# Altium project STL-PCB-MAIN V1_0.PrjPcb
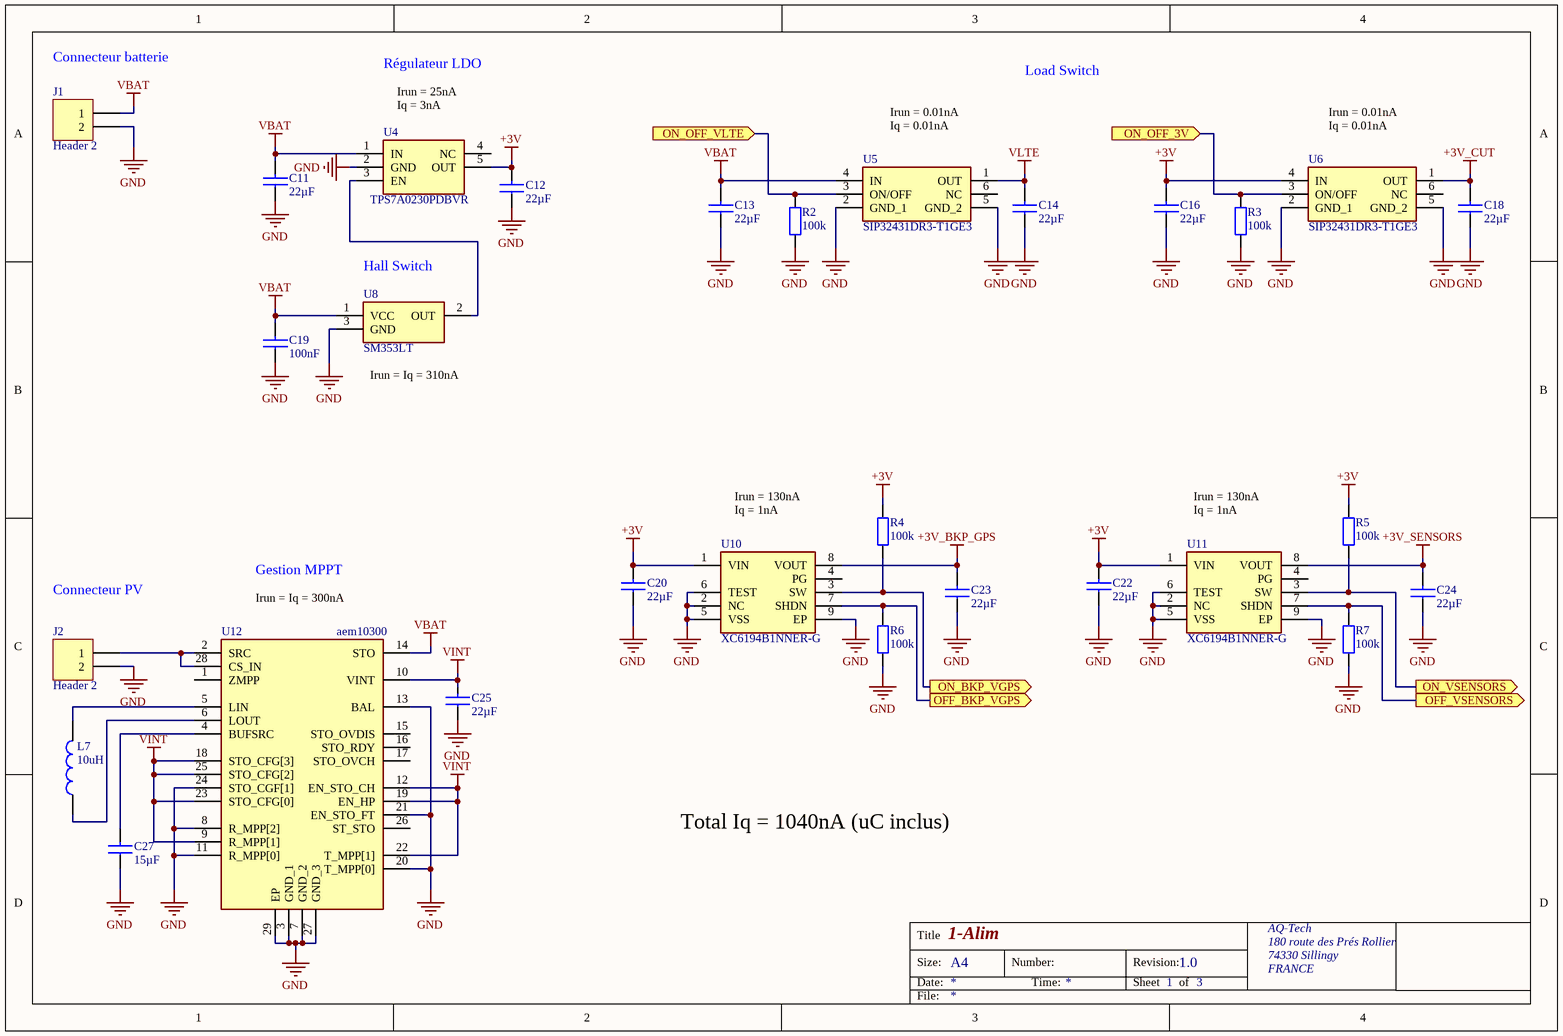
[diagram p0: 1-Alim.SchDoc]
Revision: 2.0
4 sheets, 79 parts. Net scope: flat (ports and power ports of the same name join across sheets).
Board file: STL-PCB-MAIN V1_0.PcbDoc
Sheets:
  1-Alim.SchDoc
  2-Micro.SchDoc
  3-Modules.SchDoc
  4-Capteurs.SchDoc

## Sheet 1-Alim.SchDoc: DEV-09-17 MERE
size A4; Date: 22/11/2017; Organization: Altium Limited; Address1: L3, 12a Rodborough Rd; Address2: Frenchs Forest; Address3: NSW; Address4: Australia 2086; Revision: 1.0; SheetNumber: 2; SheetTotal: 4; PageSetup: Record=PageOptions¦CenterHorizontal=True¦CenterVertical=True¦PrintScale=0.97¦XCorrection=1.00¦YCorrection=1.00¦PrintKind=0¦BorderSize=5000000¦LeftOffset=0¦BottomOffset=0¦Orientation=2¦PaperLength=1000¦PaperWidth=1000¦Scale=100¦PaperSource=7¦PrintQuality=-3¦MediaType=1¦DitherType=10¦PaperKind=A4¦PrintScaleMode=1

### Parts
C11  22µF  [CAP_0402_0H80]
C12  22µF  [CAP_0402_0H80]
C13  22µF  [CAP_0402_0H80]
C14  22µF  [CAP_0402_0H80]
C16  22µF  [CAP_0402_0H80]
C18  22µF  [CAP_0402_0H80]
C19  100nF  [CAP_0402_0H80]
C20  22µF  [CAP_0402_0H80]
C22  22µF  [CAP_0402_0H80]
C23  22µF  [CAP_0402_0H80]
C24  22µF  [CAP_0402_0H80]
C25  22µF  [CAP_0402_0H80]
C27  15µF  [CAP_0402_0H80]
J1  Header 2  [2PLAGES-2X1.3mm]
J2  Header 2  [2PLAGES-2X1.3mm]
L7  value 10uH  [VLS2520]  (hidden comment: DFE252010F-100M)
R2  100k  [RES_0402_0H65]
R3  100k  [RES_0402_0H65]
R4  100k  [RES_0402_0H65]
R5  100k  [RES_0402_0H65]
R6  100k  [RES_0402_0H65]
R7  100k  [RES_0402_0H65]
U4  TPS7A0230PDBVR  [TPS7A0230PDBVR-SOT23-5]
U5  SIP32431DR3-T1GE3  [SIP32431DR3-T1GE3]
U6  SIP32431DR3-T1GE3  [SIP32431DR3-T1GE3]
U8  SM353LT  [SOT23]
U10  XC6194B1NNER-G  [XC6194B1NNER-G]
U11  XC6194B1NNER-G  [XC6194B1NNER-G]
U12  aem10300  [AEM10300-QFN28-4X4mm]

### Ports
OFF_BKP_VGPS (out), OFF_VSENSORS (out), ON_BKP_VGPS (out), ON_OFF_3V (in), ON_OFF_VLTE (in), ON_VSENSORS (out)

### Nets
+3V: C12.2 C16.2 C20.2 C22.2 R4.2 R5.2 U4.5(OUT) U6.4(IN) U10.1(VIN) U11.1(VIN)
+3V_BKP_GPS: C23.2 U10.8(VOUT)
+3V_CUT: C18.2 U6.1(OUT)
+3V_SENSORS: C24.2 U11.8(VOUT)
GND: C11.1 C12.1 C13.1 C14.1 C16.1 C18.1 C19.1 C20.1 C22.1 C23.1 C24.1 C25.1 C27.1 J1.2 J2.2 R2.1 R3.1 R6.1 R7.1 U4.2(GND) U5.2(GND_1) U5.5(GND_2) U6.2(GND_1) U6.5(GND_2) U8.3(GND) U10.2(NC) U10.5(VSS) U10.6(TEST) U10.9(EP) U11.2(NC) U11.5(VSS) U11.6(TEST) U11.9(EP) U12.3(GND_1) U12.7(GND_2) U12.8(R_MPP[2]) U12.11(R_MPP[0]) U12.13(BAL) U12.20(T_MPP[0]) U12.21(EN_STO_FT) U12.24(STO_CGF[1]) U12.27(GND_3) U12.29(EP)
VBAT: C11.2 C13.2 C19.2 J1.1 U4.1(IN) U5.4(IN) U8.1(VCC) U12.14(STO)
VINT: C25.2 U12.9(R_MPP[1]) U12.10(VINT) U12.12(EN_STO_CH) U12.18(STO_CFG[3]) U12.19(EN_HP) U12.22(T_MPP[1]) U12.23(STO_CFG[0]) U12.25(STO_CFG[2])
VLTE: C14.2 U5.1(OUT)
ON_OFF: R3.2 U6.3(ON/OFF) ; port ON_OFF_3V
NetC27_2: C27.2 U12.4(BUFSRC)
NetJ2_1: J2.1 U12.2(SRC) U12.28(CS_IN)
NetL7_1: L7.1 U12.6(LOUT)
NetL7_2: L7.2 U12.5(LIN)
NetR2_2: R2.2 U5.3(ON/OFF) ; port ON_OFF_VLTE
NetR4_1: R4.1 U10.3(SW) ; port ON_BKP_VGPS
NetR5_1: R5.1 U11.3(SW) ; port ON_VSENSORS
NetR6_2: R6.2 U10.7(SHDN) ; port OFF_BKP_VGPS
NetR7_2: R7.2 U11.7(SHDN) ; port OFF_VSENSORS
NetU4_3: U4.3(EN) U8.2(OUT)

Not connected (* = marked no-connect by the designer): U4 4(NC); U5 6(NC); U6 6(NC); U10 4(PG); U11 4(PG); U12 1(ZMPP) 15(STO_OVDIS) 16(STO_RDY) 17(STO_OVCH) 26(ST_STO)

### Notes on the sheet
- (near J1) Connecteur batterie
- Régulateur LDO
- Irun = 25nA
- (near U4) Iq = 3nA
- Irun = 0.01nA
- Load Switch
- (near U5) Iq = 0.01nA
- (near U6) Iq = 0.01nA
- (near U8) Hall Switch
- (near U8) Irun = Iq = 310nA
- Irun = 130nA
- (near U10) Iq = 1nA
- (near U11) Iq = 1nA
- Gestion MPPT
- Connecteur PV
- (near U12) Irun = Iq = 300nA
- Total Iq = 1040nA (uC inclus)
- Title
- Size:
- Date:
- 1-Alim
- A4
- Number:
- Time:
- Revision:
- Sheet
- 1
- 1.0
- of
- 3
- AQ-Tech
- 180 route des Prés Rollier
- 74330 Sillingy
- FRANCE
- File:

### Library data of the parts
C11-C14 C16 C18 C20 C22-C25 = C0603-10µF-X5R-6.3V: Capacitor, Ceramic, 22µF, 0402, 20%, 6.3V, X5R; Ref Fabricant: Generic
C19 = C0603-100nF-X7R-50V: Capacitor, Ceramic, 100nF, 0402, 10%, 50V, X7R; Ref Fabricant: Generic
C27 = C0603-10µF-X5R-6.3V: Capacitor, Ceramic, 15µF, 0402, 20%, 6.3V, X5R; Ref Fabricant: Generic
J1 J2 = Header 2: Header, 2-Pin
L7 = MURATA-1µH-4.3A-2.5x2x1.2: SMD Power Inductor 1.76A, 0.042Ω, 10uH; Fabricant: Murata; DC Resistance: 0.042Ω max.
R2-R7 = R0603_120k_1%: Resistor, Thin Film, 100k, 1%, 65mW, 0402; Ref Fabricant: Generic; TCR: 100ppm/°C
U4 = TPS7A0212PDBVR: Integrated Circuit; Manufacturer_Name: Texas Instruments
U5 U6 = SIP32431DR3-T1GE3: Integrated Circuit; Manufacturer_Name: Vishay
U8 = SM353LT: Integrated Circuit; Manufacturer_Name: Honeywell
U10 U11 = XC6194B1NNER-G: Integrated Circuit; Manufacturer_Name: Torex
U12 = aem10300: Integrated Circuit; Manufacturer_Name: E-PEAS; Manufacturer_Part_Number: aem10900

## Sheet 2-Micro.SchDoc: DEV-09-17 MERE
size A4; Date: 22/11/2017; Organization: Altium Limited; Address1: L3, 12a Rodborough Rd; Address2: Frenchs Forest; Address3: NSW; Address4: Australia 2086; Revision: 1.0; SheetNumber: 2; SheetTotal: 4; PageSetup: Record=PageOptions¦CenterHorizontal=True¦CenterVertical=True¦PrintScale=0.97¦XCorrection=1.00¦YCorrection=1.00¦PrintKind=0¦BorderSize=5000000¦LeftOffset=0¦BottomOffset=0¦Orientation=2¦PaperLength=1000¦PaperWidth=1000¦Scale=100¦PaperSource=7¦PrintQuality=-3¦MediaType=1¦DitherType=10¦PaperKind=A4¦PrintScaleMode=1
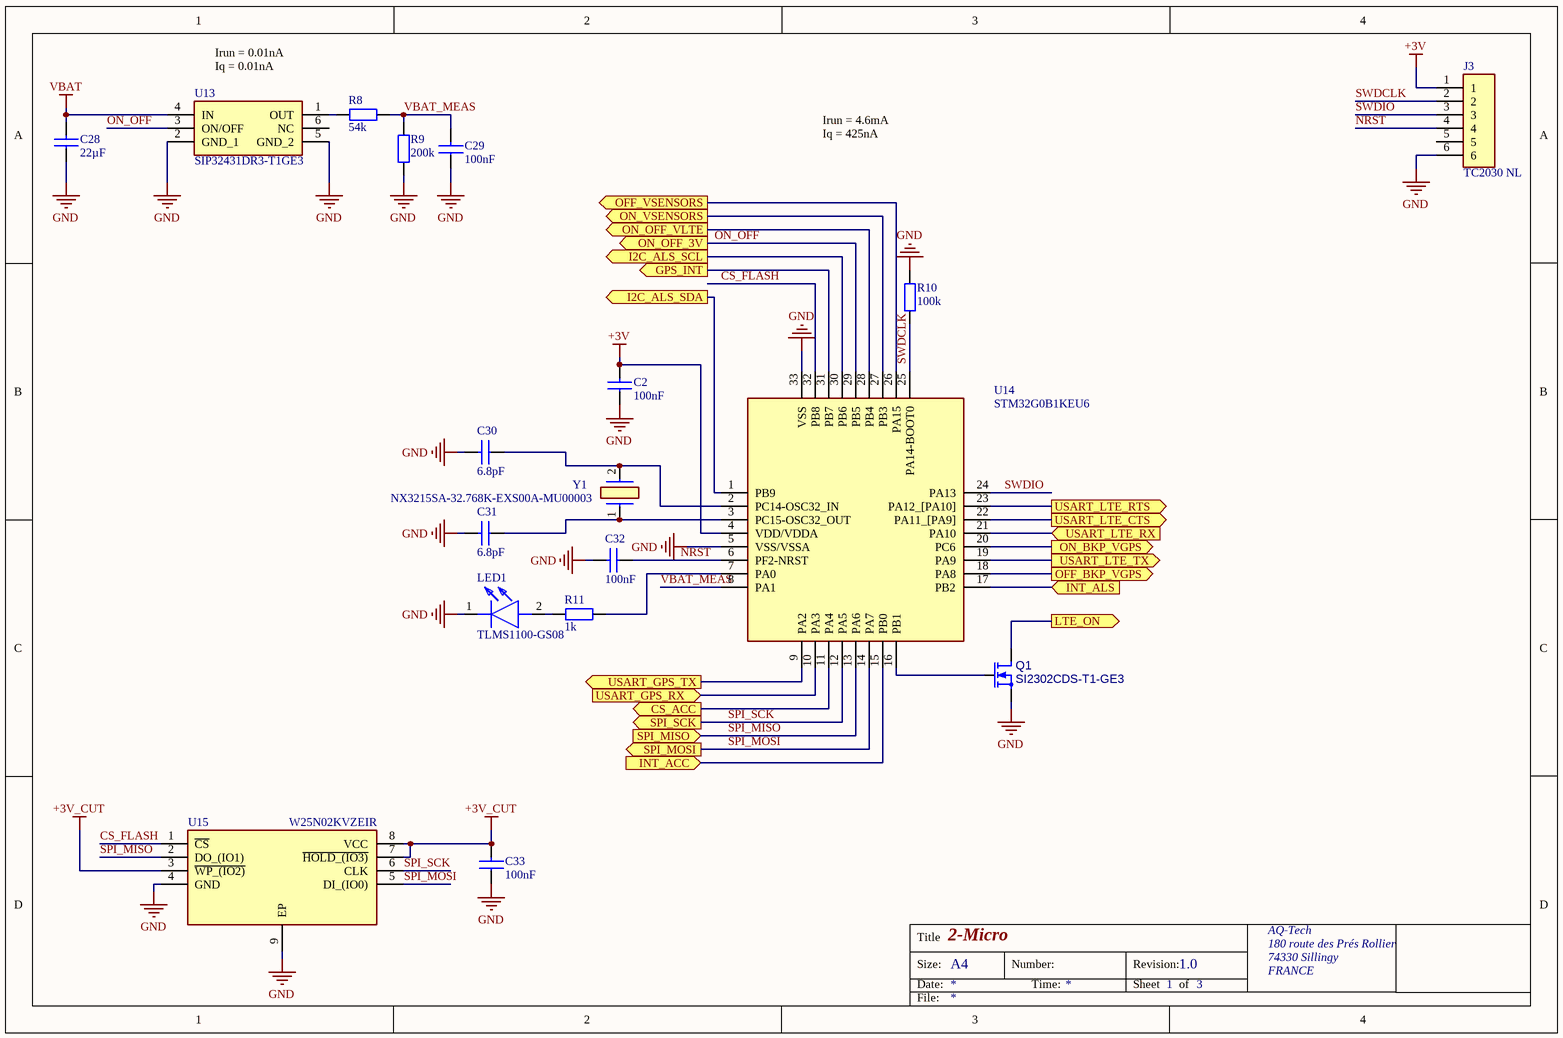
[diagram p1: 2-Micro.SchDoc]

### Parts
C2  100nF  [CAP_0402_0H80]
C28  22µF  [CAP_0402_0H80]
C29  100nF  [CAP_0402_0H80]
C30  6.8pF  [CAP_0402_0H80]
C31  6.8pF  [CAP_0402_0H80]
C32  100nF  [CAP_0402_0H80]
C33  100nF  [CAP_0402_0H80]
J3  TC2030 NL  [TC2030MCPNL10]
LED1  TLMS1100-GS08  [LED_150060VS7500]
Q1  SI2302CDS-T1-GE3  [SOT23]
R8  54k  [RES_0402_0H65]
R9  200k  [RES_0402_0H65]
R10  100k  [RES_0402_0H65]
R11  1k  [RES_0402_0H65]
U13  SIP32431DR3-T1GE3  [SIP32431DR3-T1GE3]
U14  STM32G0B1KEU6  [STM32G0B1KEU6]
U15  W25N02KVZEIR  [W25N02KVZEIR]
Y1  NX3215SA-32.768K-EXS00A-MU00003  [NX3215SA]

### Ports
CS_ACC (out), GPS_INT (out), I2C_ALS_SCL (out), I2C_ALS_SDA (out), INT_ACC (in), INT_ALS (in), LTE_ON (out), OFF_BKP_VGPS (out), OFF_VSENSORS (out), ON_BKP_VGPS (out), ON_OFF_3V (out), ON_OFF_VLTE (out), ON_VSENSORS (out), SPI_MISO (in), SPI_MOSI (out), SPI_SCK (out), USART_GPS_RX (in), USART_GPS_TX (out), USART_LTE_CTS (out), USART_LTE_RTS (out), USART_LTE_RX (in), USART_LTE_TX (out)

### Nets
+3V: C2.2 J3.1 U14.4(VDD/VDDA)
+3V_CUT: C33.2 U15.3(~{WP_(IO2)}) U15.7(~{HOLD_(IO3)}) U15.8(VCC)
GND: C2.1 C28.1 C29.1 C30.2 C31.2 C32.2 C33.1 J3.6 LED1.1(K) Q1.2(S) R9.1 R10.2 U13.2(GND_1) U13.5(GND_2) U14.5(VSS/VSSA) U14.33(VSS) U15.4(GND) U15.9(EP)
VBAT: C28.2 U13.4(IN)
CS_FLASH: U14.32(PB8) U15.1(~{CS})
NRST: C32.1 J3.4 U14.6(PF2-NRST)
ON_OFF: U13.3(ON/OFF) U14.29(PB5) ; port ON_OFF_3V
SPI_MISO: U14.13(PA6) U15.2(DO_(IO1)) ; port SPI_MISO
SPI_MOSI: U14.14(PA7) U15.5(DI_(IO0)) ; port SPI_MOSI
SPI_SCK: U14.12(PA5) U15.6(CLK) ; port SPI_SCK
SWDCLK: J3.2 R10.1 U14.25(PA14-BOOT0)
SWDIO: J3.3 U14.24(PA13)
VBAT_MEAS: C29.2 R8.1 R9.2 U14.8(PA1)
NetC30_1: C30.1 U14.2(PC14-OSC32_IN) Y1.2
NetC31_1: C31.1 U14.3(PC15-OSC32_OUT) Y1.1
NetLED1_2: LED1.2(A) R11.1
NetQ1_1: Q1.1(G) U14.16(PB1)
NetQ1_3: Q1.3(D) ; port LTE_ON
NetR2_2: U14.28(PB4) ; port ON_OFF_VLTE
NetR4_1: U14.20(PC6) ; port ON_BKP_VGPS
NetR5_1: U14.27(PB3) ; port ON_VSENSORS
NetR6_2: U14.18(PA8) ; port OFF_BKP_VGPS
NetR7_2: U14.26(PA15) ; port OFF_VSENSORS
NetR8_2: R8.2 U13.1(OUT)
NetR11_2: R11.2 U14.7(PA0)
NetR12_1: U14.17(PB2) ; port INT_ALS
NetU2_13: U14.10(PA3) ; port USART_GPS_RX
NetU2_14: U14.9(PA2) ; port USART_GPS_TX
NetU2_19: U14.31(PB7) ; port GPS_INT
NetU3_7: U14.22(PA11_[PA9]) ; port USART_LTE_CTS
NetU3_8: U14.23(PA12_[PA10]) ; port USART_LTE_RTS
NetU3_9: U14.19(PA9) ; port USART_LTE_TX
NetU3_10: U14.21(PA10) ; port USART_LTE_RX
NetU14_1: U14.1(PB9) ; port I2C_ALS_SDA
NetU14_11: U14.11(PA4) ; port CS_ACC
NetU14_15: U14.15(PB0) ; port INT_ACC
NetU14_30: U14.30(PB6) ; port I2C_ALS_SCL

Not connected (* = marked no-connect by the designer): J3 5; U13 6(NC)

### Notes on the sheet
- Irun = 0.01nA
- (near U13) Iq = 0.01nA
- Irun = 4.6mA
- Iq = 425nA
- Title
- Size:
- Date:
- 2-Micro
- A4
- Number:
- Time:
- Revision:
- Sheet
- 1
- 1.0
- of
- 3
- AQ-Tech
- 180 route des Prés Rollier
- 74330 Sillingy
- FRANCE
- File:

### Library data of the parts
C2 C29 C32 C33 = C0603-100nF-X7R-50V: as C19 on sheet 1-Alim
C28 = C0603-10µF-X5R-6.3V: as C11 on sheet 1-Alim
C30 C31 = C0603-100nF-X7R-50V: Capacitor, Ceramic, 6.8pF, 0402, 5%, 50V, COG; Ref Fabricant: Generic
J3 = TC2030-MCP-NL-10: Connector; Manufacturer_Name: Tag Connect
LED1 = 150060VS75000: LED; Manufacturer_Name: Vishay
Q1 = 2N7002F: Transistor Mosfet SI2302CDS-T1-GE3, 385mA canal N, SOT23; Prix: 0.059 €; Fabricant: NXP; Fournisseur: Farnell; Ref Fournisseur: 1894722
R8-R11 = R0603_120k_1%: as R2 on sheet 1-Alim
U13 = SIP32431DR3-T1GE3: as U5 on sheet 1-Alim
U14 = STM32G0B1KEU6: Integrated Circuit; Manufacturer_Name: STMicroelectronics
U15 = W25N02KVZEIR: Integrated Circuit; Manufacturer_Name: Winbond
Y1 = NX3215SA-32.768K-EXS00A-MU00003: Crystal or Oscillator; Manufacturer_Name: NDK

## Sheet 3-Modules.SchDoc: DEV-09-17 MERE
size A4; Date: 22/11/2017; Organization: Altium Limited; Address1: L3, 12a Rodborough Rd; Address2: Frenchs Forest; Address3: NSW; Address4: Australia 2086; Revision: 1.0; SheetNumber: 2; SheetTotal: 4; PageSetup: Record=PageOptions¦CenterHorizontal=True¦CenterVertical=True¦PrintScale=0.97¦XCorrection=1.00¦YCorrection=1.00¦PrintKind=0¦BorderSize=5000000¦LeftOffset=0¦BottomOffset=0¦Orientation=2¦PaperLength=1000¦PaperWidth=1000¦Scale=100¦PaperSource=7¦PrintQuality=-3¦MediaType=1¦DitherType=10¦PaperKind=A4¦PrintScaleMode=1
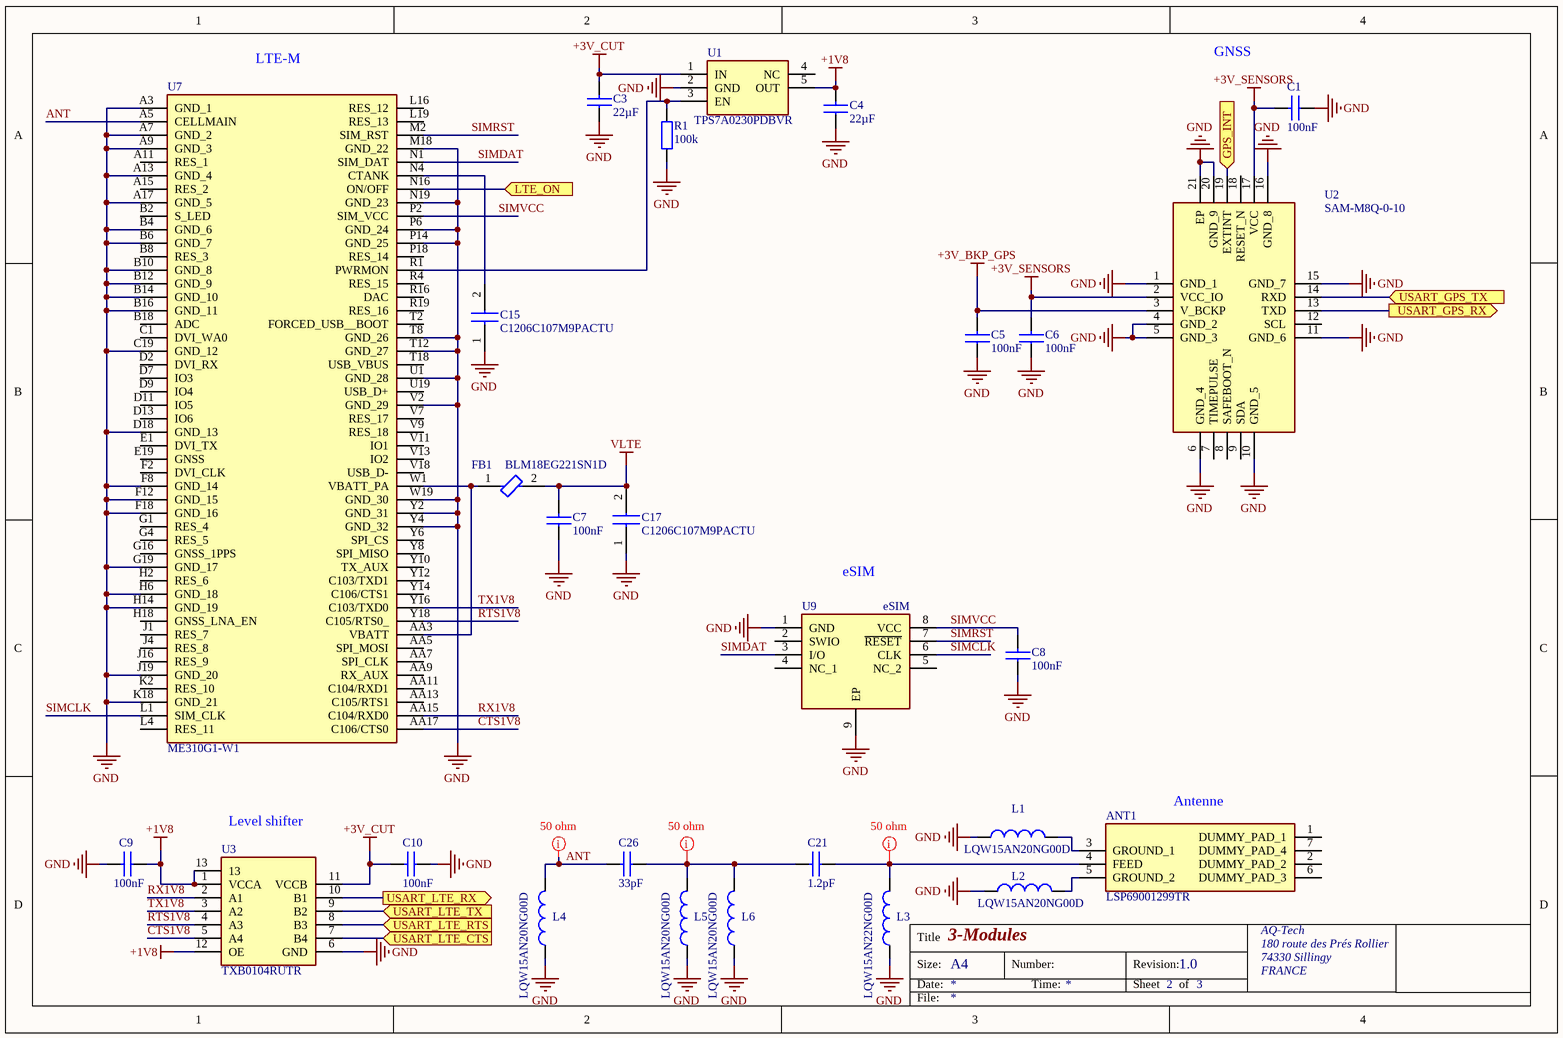
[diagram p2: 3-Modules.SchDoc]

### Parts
ANT1  LSP69001299TR  [ANT-LSP69001299TR]
C1  100nF  [CAP_0402_0H80]
C3  22µF  [CAP_0402_0H80]
C4  22µF  [CAP_0402_0H80]
C5  100nF  [CAP_0402_0H80]
C6  100nF  [CAP_0402_0H80]
C7  100nF  [CAP_0402_0H80]
C8  100nF  [CAP_0402_0H80]
C9  100nF  [CAP_0402_0H80]
C10  100nF  [CAP_0402_0H80]
C15  C1206C107M9PACTU  [CAP_1206_1H90]
C17  C1206C107M9PACTU  [CAP_1206_1H90]
C21  1.2pF  [CAP_0402_0H80]
C26  33pF  [CAP_0402_0H80]
FB1  BLM18EG221SN1D  [BLM18EG101TN1B]
L1  LQW15AN20NG00D  [IND_LQW15AN]
L2  LQW15AN20NG00D  [IND_LQW15AN]
L3  LQW15AN22NG00D  [IND_LQW15AN]
L4  LQW15AN20NG00D  [IND_LQW15AN]
L5  LQW15AN20NG00D  [IND_LQW15AN]
L6  LQW15AN20NG00D  [IND_LQW15AN]
R1  100k  [RES_0402_0H65]
U1  TPS7A0230PDBVR  [TPS7A0230PDBVR-SOT23-5]
U2  SAM-M8Q-0-10  [SAMM8Q010]
U3  TXB0104RUTR  [TXB0104RUTR]
U7  ME310G1-W1  [ME310G1-W1]
U9  eSIM  [ST4SI2M0020TPIFW]

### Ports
GPS_INT (in), LTE_ON (in), USART_GPS_RX (out), USART_GPS_TX (in), USART_LTE_CTS (in), USART_LTE_RTS (in), USART_LTE_RX (out), USART_LTE_TX (in)

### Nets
+1V8: C4.2 C9.1 U1.5(OUT) U3.1(VCCA) U3.12(OE) U3.13
+3V_BKP_GPS: C5.2 U2.3(V_BCKP)
+3V_CUT: C3.2 C10.2 U1.1(IN) U3.11(VCCB)
+3V_SENSORS: C1.2 C6.2 U2.2(VCC_IO) U2.17(VCC)
GND: C1.1 C3.1 C4.1 C5.1 C6.1 C7.1 C8.1 C9.2 C10.1 C15.1 C17.1 L1.1 L2.1 L3.1 L4.1 L5.1 L6.1 R1.1 U1.2(GND) U2.1(GND_1) U2.4(GND_2) U2.5(GND_3) U2.6(GND_4) U2.10(GND_5) U2.11(GND_6) U2.15(GND_7) U2.16(GND_8) U2.20(GND_9) U2.21(EP) U3.6(GND) U7.A3(GND_1) U7.A7(GND_2) U7.A9(GND_3) U7.A13(GND_4) U7.A17(GND_5) U7.B4(GND_6) U7.B6(GND_7) U7.B10(GND_8) U7.B12(GND_9) U7.B14(GND_10) U7.B16(GND_11) U7.C19(GND_12) U7.D18(GND_13) U7.F8(GND_14) U7.F12(GND_15) U7.F18(GND_16) U7.G19(GND_17) U7.H6(GND_18) U7.H14(GND_19) U7.J19(GND_20) U7.K18(GND_21) U7.M18(GND_22) U7.N19(GND_23) U7.P6(GND_24) U7.P14(GND_25) U7.T8(GND_26) U7.T12(GND_27) U7.U1(GND_28) U7.V2(GND_29) U7.W19(GND_30) U7.Y2(GND_31) U7.Y4(GND_32) U9.1(GND) U9.9(EP)
VLTE: C7.2 C17.2 FB1.2
ANT: C26.2 L4.2 U7.A5(CELLMAIN)
CTS1V8: U3.5(A4) U7.AA17(C106/CTS0)
RTS1V8: U3.4(A3) U7.Y18(C105/RTS0_)
RX1V8: U3.2(A1) U7.AA15(C104/RXD0)
SIMCLK: U7.L1(SIM_CLK) U9.6(CLK)
SIMDAT: U7.N1(SIM_DAT) U9.3(I/O)
SIMRST: U7.M2(SIM_RST) U9.7(~{RESET})
SIMVCC: C8.2 U7.P2(SIM_VCC) U9.8(VCC)
TX1V8: U3.3(A2) U7.Y16(C103/TXD0)
NetANT1_3: ANT1.3(GROUND_1) L1.2
NetANT1_4: ANT1.4(FEED) C21.1 L3.2
NetANT1_5: ANT1.5(GROUND_2) L2.2
NetC15_2: C15.2 U7.N4(CTANK)
NetC21_2: C21.2 C26.1 L5.2 L6.2
NetFB1_1: FB1.1 U7.AA3(VBATT) U7.W1(VBATT_PA)
NetQ1_3: U7.N16(ON/OFF) ; port LTE_ON
NetR1_2: R1.2 U1.3(EN) U7.R1(PWRMON)
NetU2_13: U2.13(TXD) ; port USART_GPS_RX
NetU2_14: U2.14(RXD) ; port USART_GPS_TX
NetU2_19: U2.19(EXTINT) ; port GPS_INT
NetU3_7: U3.7(B4) ; port USART_LTE_CTS
NetU3_8: U3.8(B3) ; port USART_LTE_RTS
NetU3_9: U3.9(B2) ; port USART_LTE_TX
NetU3_10: U3.10(B1) ; port USART_LTE_RX

Not connected (* = marked no-connect by the designer): ANT1 1(DUMMY_PAD_1) 2(DUMMY_PAD_2) 6(DUMMY_PAD_3) 7(DUMMY_PAD_4); U1 4(NC); U2 7(TIMEPULSE) 8(SAFEBOOT_N) 9(SDA) 12(SCL) 18(RESET_N); U7 A11(RES_1) A15(RES_2) AA5(SPI_MOSI) AA7(SPI_CLK) AA9(RX_AUX) AA11(C104/RXD1) AA13(C105/RTS1) B2(S_LED) B8(RES_3) B18(ADC) C1(DVI_WA0) D2(DVI_RX) D7(IO3) D9(IO4) D11(IO5) D13(IO6) E1(DVI_TX) E19(GNSS) F2(DVI_CLK) G1(RES_4) G4(RES_5) G16(GNSS_1PPS) H2(RES_6) H18(GNSS_LNA_EN) J1(RES_7) J4(RES_8) J16(RES_9) K2(RES_10) L4(RES_11) L16(RES_12) L19(RES_13) P18(RES_14) R4(RES_15) R16(DAC) R19(RES_16) T2(FORCED_USB__BOOT) T18(USB_VBUS) U19(USB_D+) V7(RES_17) V9(RES_18) V11(IO1) V13(IO2) V18(USB_D-) Y6(SPI_CS) Y8(SPI_MISO) Y10(TX_AUX) Y12(C103/TXD1) Y14(C106/CTS1); U9 2(SWIO) 4(NC_1) 5(NC_2)

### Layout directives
net class 50ohms: ANT, NetANT1_4, NetC21_2

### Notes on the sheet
- (near U7) LTE-M
- GNSS
- (near U9) eSIM
- (near U3) Level shifter
- (near ANT1) Antenne
- (near L3) Title
- (near L3) Size:
- (near L3) Date:
- (near L2) 3-Modules
- A4
- Number:
- Time:
- Revision:
- Sheet
- 2
- 1.0
- of
- 3
- (near ANT1) AQ-Tech
- FRANCE
- 180 route des Prés Rollier
- 74330 Sillingy
- File:

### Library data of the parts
ANT1 = LSP69001299TR: Antenna; Manufacturer_Name: AVX
C1 C5-C10 = C0603-100nF-X7R-50V: as C19 on sheet 1-Alim
C3 C4 = C0603-10µF-X5R-6.3V: as C11 on sheet 1-Alim
C15 C17 = C1206C107M9PACTU: Capacitor; Manufacturer_Name: KEMET
C21 = C0603-100nF-X7R-50V: Capacitor, Ceramic, 1.2pF, 0603, +/-0.25pF, 50V; Ref Fabricant: Generic; Dielectric: COG
C26 = C0603-100nF-X7R-50V: Capacitor, Ceramic, 33pF, 0603, 5%, 50V, X7R; Ref Fabricant: Generic
FB1 = 5f30dd21d616792df468990f7003faa: Chip Ferrite Bead, 0603, 100Ω @ 100MHz, 25%, 0.045Ω, 2A; Manufacturer_Name: Murata; Impedance: 100R; DC Resistance (DCR): 45mR
L1 L2 L4-L6 = Inductor: Wire Wound RF Inductor 20nH ±2% 370mA 0.27Ω 0402 (1005); Manufacturer_Name: Murata; Code_IEC: 1005
L3 = Inductor: Wire Wound RF Inductor 22nH ±2% 370mA 0.27Ω 0402 (1005); Manufacturer_Name: Murata; Code_IEC: 1005
R1 = R0603_120k_1%: as R2 on sheet 1-Alim
U1 = TPS7A0212PDBVR: as U4 on sheet 1-Alim
U2 = SAM-M8Q-0-10: Integrated Circuit; Manufacturer_Name: U-Blox
U3 = TXB0104RUTR: Integrated Circuit; Manufacturer_Name: Texas Instruments
U7 = ME310G1-W1: Integrated Circuit; Manufacturer_Name: Telit Wireless Solutions
U9 = ST4SI2M0020TPIFW: Integrated Circuit; Manufacturer_Name: STMicroelectronics

## Sheet 4-Capteurs.SchDoc: DEV-09-17 MERE
size A4; Date: 22/11/2017; Organization: Altium Limited; Address1: L3, 12a Rodborough Rd; Address2: Frenchs Forest; Address3: NSW; Address4: Australia 2086; Revision: 1.0; SheetNumber: 2; SheetTotal: 4; PageSetup: Record=PageOptions¦CenterHorizontal=True¦CenterVertical=True¦PrintScale=0.97¦XCorrection=1.00¦YCorrection=1.00¦PrintKind=0¦BorderSize=5000000¦LeftOffset=0¦BottomOffset=0¦Orientation=2¦PaperLength=1000¦PaperWidth=1000¦Scale=100¦PaperSource=7¦PrintQuality=-3¦MediaType=1¦DitherType=10¦PaperKind=A4¦PrintScaleMode=1
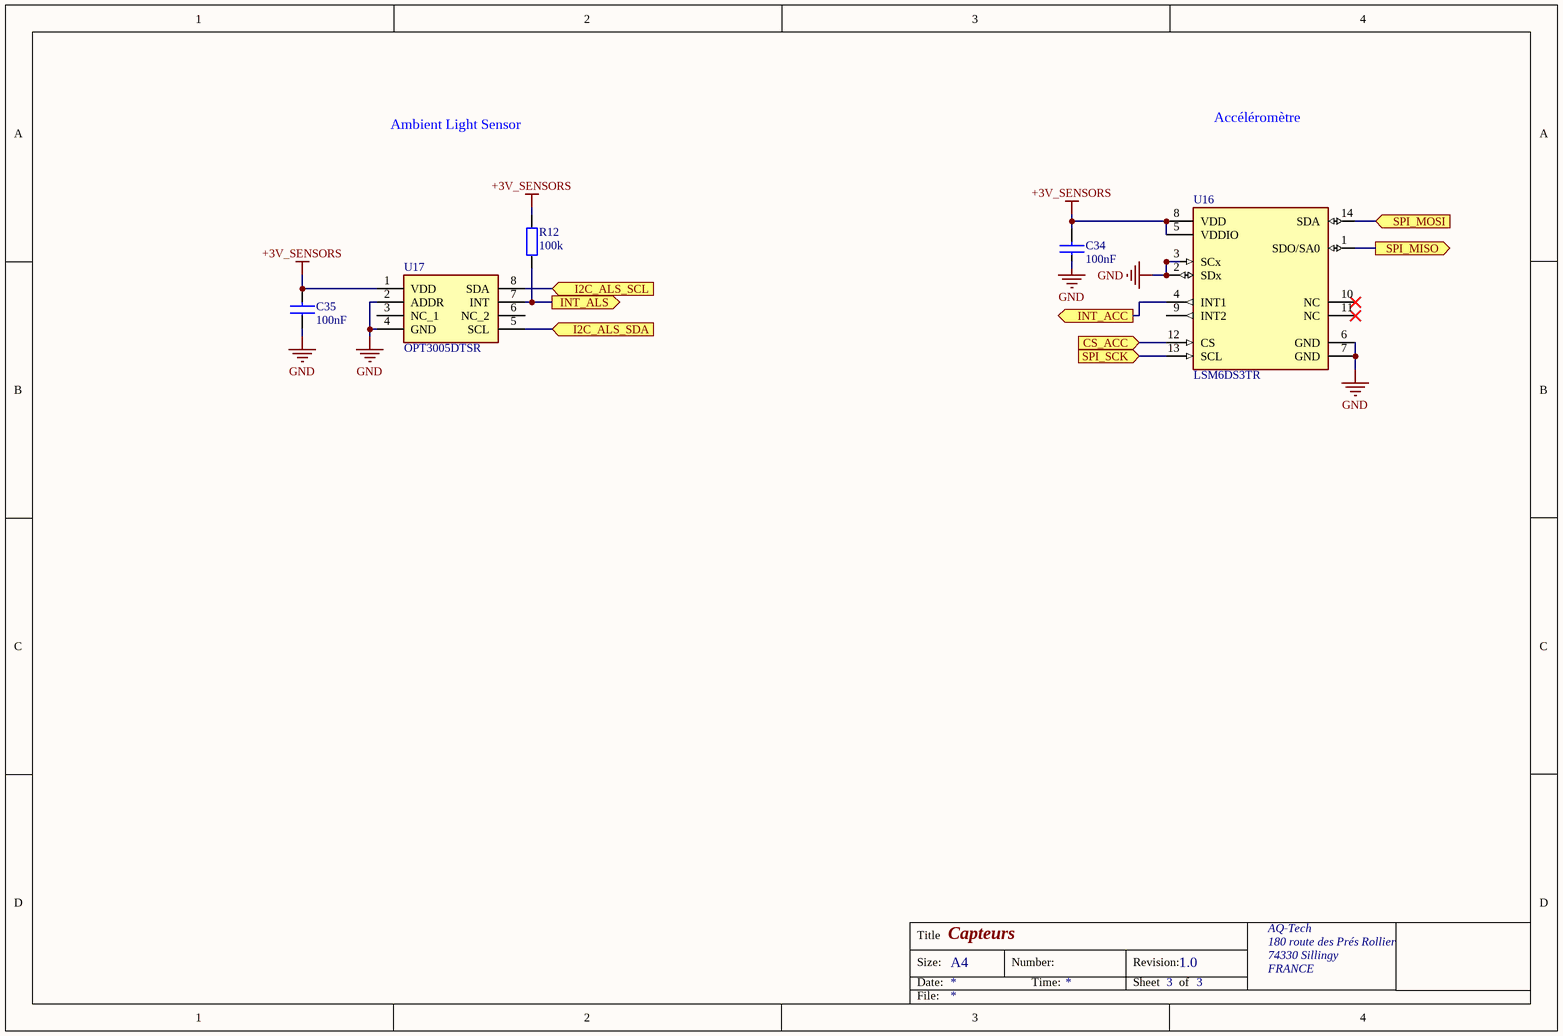
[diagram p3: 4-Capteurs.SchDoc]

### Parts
C34  100nF  [CAP_0402_0H80]
C35  100nF  [CAP_0402_0H80]
R12  100k  [RES_0402_0H65]
U16  LSM6DS3TR  [LSM6DSOTR-LGA14]
U17  OPT3005DTSR  [OPT3005DTSR]

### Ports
CS_ACC (in), I2C_ALS_SCL (in), I2C_ALS_SDA (in), INT_ACC (out), INT_ALS (out), SPI_MISO (out), SPI_MOSI (in), SPI_SCK (in)

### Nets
+3V_SENSORS: C34.2 C35.2 R12.2 U16.5(VDDIO) U16.8(VDD) U17.1(VDD)
GND: C34.1 C35.1 U16.2(SDx) U16.3(SCx) U16.6(GND) U16.7(GND) U17.2(ADDR) U17.4(GND)
SPI_MISO: U16.1(SDO/SA0) ; port SPI_MISO
SPI_MOSI: U16.14(SDA) ; port SPI_MOSI
SPI_SCK: U16.13(SCL) ; port SPI_SCK
NetR12_1: R12.1 U17.7(INT) ; port INT_ALS
NetU14_1: U17.5(SCL) ; port I2C_ALS_SDA
NetU14_11: U16.12(CS) ; port CS_ACC
NetU14_15: U16.4(INT1) ; port INT_ACC
NetU14_30: U17.8(SDA) ; port I2C_ALS_SCL

Not connected (* = marked no-connect by the designer): U16 9(INT2) 10(NC)* 11(NC)*; U17 3(NC_1) 6(NC_2)

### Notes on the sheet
- Ambient Light Sensor
- Accéléromètre
- Title
- Size:
- Date:
- Capteurs
- A4
- Number:
- Time:
- Revision:
- Sheet
- 3
- 1.0
- of
- AQ-Tech
- FRANCE
- 180 route des Prés Rollier
- 74330 Sillingy
- File:

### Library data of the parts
C34 C35 = C0603-100nF-X7R-50V: as C19 on sheet 1-Alim
R12 = R0603_120k_1%: as R2 on sheet 1-Alim
U16 = 7257f23b88fab88f30c8b27feb514af: IMU ACCEL/GYRO I2C/SPI 14VFLGA; Manufacturer: STMicroelectronics; Sensor Type: Temperature,Accelerometer,Gyroscope; Gyro Range: 125/250/500/1000/2000°/s; Min Supply Voltage: 1.62V; Operating Supply Current: 9-900uA; Accel Range: 2/4/8/16g; Max Supply Voltage: 3.6V; Sensor Output: I2C,SPI
U17 = OPT3005DTSR: Integrated Circuit; Manufacturer_Name: Texas Instruments

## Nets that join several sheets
+3V: 1-Alim (10 pins), 2-Micro (C2.2 J3.1 U14.4)
+3V_BKP_GPS: 1-Alim (C23.2 U10.8), 3-Modules (C5.2 U2.3)
+3V_CUT: 1-Alim (C18.2 U6.1), 2-Micro (C33.2 U15.3 U15.7 U15.8), 3-Modules (C3.2 C10.2 U1.1 U3.11)
+3V_SENSORS: 1-Alim (C24.2 U11.8), 3-Modules (C1.2 C6.2 U2.2 U2.17), 4-Capteurs (6 pins)
GND: 1-Alim (43 pins), 2-Micro (18 pins), 3-Modules (64 pins), 4-Capteurs (8 pins)
VBAT: 1-Alim (8 pins), 2-Micro (C28.2 U13.4)
VLTE: 1-Alim (C14.2 U5.1), 3-Modules (C7.2 C17.2 FB1.2)
NetQ1_3: 2-Micro (Q1.3), 3-Modules (U7.N16)
NetR2_2: 1-Alim (R2.2 U5.3), 2-Micro (U14.28)
NetR4_1: 1-Alim (R4.1 U10.3), 2-Micro (U14.20)
NetR5_1: 1-Alim (R5.1 U11.3), 2-Micro (U14.27)
NetR6_2: 1-Alim (R6.2 U10.7), 2-Micro (U14.18)
NetR7_2: 1-Alim (R7.2 U11.7), 2-Micro (U14.26)
NetR12_1: 2-Micro (U14.17), 4-Capteurs (R12.1 U17.7)
NetU2_13: 2-Micro (U14.10), 3-Modules (U2.13)
NetU2_14: 2-Micro (U14.9), 3-Modules (U2.14)
NetU2_19: 2-Micro (U14.31), 3-Modules (U2.19)
NetU3_7: 2-Micro (U14.22), 3-Modules (U3.7)
NetU3_8: 2-Micro (U14.23), 3-Modules (U3.8)
NetU3_9: 2-Micro (U14.19), 3-Modules (U3.9)
NetU3_10: 2-Micro (U14.21), 3-Modules (U3.10)
NetU14_1: 2-Micro (U14.1), 4-Capteurs (U17.5)
NetU14_11: 2-Micro (U14.11), 4-Capteurs (U16.12)
NetU14_15: 2-Micro (U14.15), 4-Capteurs (U16.4)
NetU14_30: 2-Micro (U14.30), 4-Capteurs (U17.8)
ON_OFF: 1-Alim (R3.2 U6.3), 2-Micro (U13.3 U14.29)
SPI_MISO: 2-Micro (U14.13 U15.2), 4-Capteurs (U16.1)
SPI_MOSI: 2-Micro (U14.14 U15.5), 4-Capteurs (U16.14)
SPI_SCK: 2-Micro (U14.12 U15.6), 4-Capteurs (U16.13)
